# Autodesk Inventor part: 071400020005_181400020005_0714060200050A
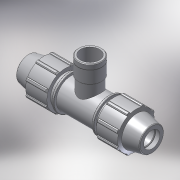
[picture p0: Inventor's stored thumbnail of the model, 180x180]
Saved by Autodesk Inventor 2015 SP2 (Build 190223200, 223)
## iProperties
Created: 2017-02
Part Number: 071400020005_181400020005_0714060200050A
Material: PVC-Piping
Description: PLASSON TEE WITH THREADED FEMALE OFFTAKE 20-1/2"-20
Document SubType Name: Modeling
Designer: KIM
Mass: 92.6774 g
Surface Area: 199.44 cm^2
Volume: 66.1981 cm^3
Density: 1.4 g/cm^3
Appearance: Smooth - White
Author: KIM
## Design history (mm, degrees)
derived "07140.ipt"
feature "Solid1::07140.ipt"
feature "Solid2::07140.ipt"
tag "TaggingFeature1"
body "Solid1"
other parameters: "d4" = 6, "d5" = 17.28, "d7" = 48, "d11" = 2.4, "d13" = 120 deg, "d15" = 12 deg, "d16" = 41.76, "d18" = 1, "d19" = 35 deg, "d20" = 17.5 deg, "d21" = 44.64, "d23" = 0, "d25" = 360 deg, "d27" = 0.96, "d33" = 0.4, "d42" = 25.92, "d43" = 1.44, "d46" = 0.6, "d68" = 4.32, "d72" = 42, "d76" = 18.631, "d80" = 0.55893, "d91" = 36, "d93" = 56, "d95" = 18, "d112" = 18, "d115" = 23.28875, "d116" = 135 deg, "d117" = 21.42565, "d118" = 144, "d119" = 18, "d121" = 0, "d122" = 18, "d124" = 0, "d128" = 0, "d129" = 2, "d130" = 5.4, "d131" = 0.3, "d132" = 0.3, "d133" = 23.28875, "E_" = 48, "A_" = 42, "l_" = 56, "l_2" = 18, "Rp_" = 18.631, "H_" = 144
